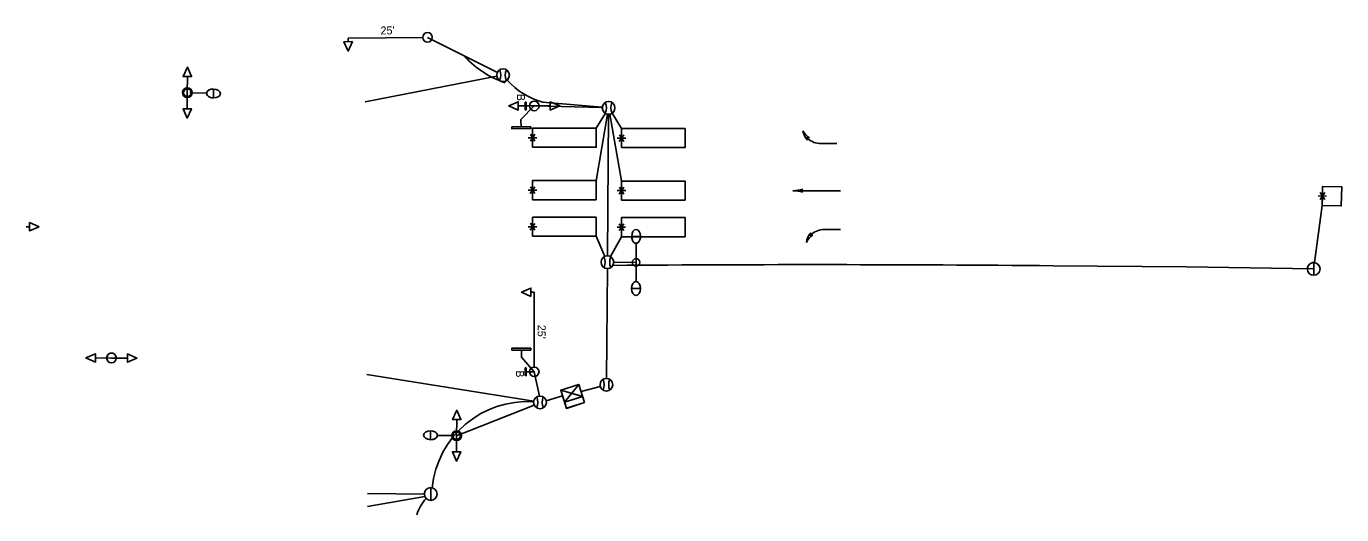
# Model space of a CAD drawing. Extents: x 596176 to 605330, y 332416 to 402398.
# Drawn here: x 602042.7 to 602456.7, y 376707.3 to 376860.8 of the extents above; entities that cross this region are included whole.
import ezdxf

# ---------------------------------------------------------------- set-up
doc = ezdxf.new("R2010")
doc.units = 0
for name, color, linetype in [('E_SIG', 7, 'Continuous'), ('P_LTG', 7, 'Continuous'), ('P_SIG', 7, 'Continuous'), ('P_SIG_Conduit', 7, 'Continuous'), ('P_SIG_IC', 7, 'Continuous'), ('P_SIG_Loops', 7, 'Continuous')]:
    doc.layers.add(name, color=color, linetype=linetype)

# ---------------------------------------------------------------- blocks, each defined once
blk = doc.blocks.new('_U234')
at = {"layer": 'E_SIG'}
for p, q in [((-0.114, 0.076), (0.114, 0.076)), ((-0.114, 0.076), (0.114, -0.076)), ((0.114, 0.076), (-0.114, -0.076))]:
    blk.add_line(p, q, dxfattribs=at)
blk.add_lwpolyline([(-0.114, 0.152), (0.114, 0.152), (0.114, -0.076), (-0.114, -0.076)], close=True, dxfattribs=at)

msp = doc.modelspace()

# ---------------------------------------------------------------- linework, layer by layer
at = {"layer": 'P_LTG'}
for p, q in [((602094.11, 376839.92), (602099.4, 376839.78)), ((602101.55, 376838.32), (602101.63, 376841.09)), ((602236.01, 376794.77), (602233.23, 376794.77)), ((602234.61, 376786.57), (602234.61, 376792.64)), ((602234.61, 376786.57), (602234.61, 376780.57)), ((602233.2, 376778.37), (602235.98, 376778.37)), ((602169.92, 376733.61), (602169.89, 376730.83)), ((602177.39, 376732.12), (602172.09, 376732.18))]:
    msp.add_line(p, q, dxfattribs=at)
for centre in [(602093.4, 376839.94), (602234.61, 376786.58), (602178.09, 376732.11)]:
    msp.add_circle(centre, 1.21, dxfattribs=at)
for centre, major_axis in [((602101.59, 376839.7), (2.18, -0.06)), ((602234.62, 376794.77), (0, 2.18)), ((602234.59, 376778.37), (0, -2.18)), ((602169.9, 376732.22), (-2.18, 0.03))]:
    msp.add_ellipse(centre, major_axis=major_axis, ratio=0.636439, start_param=1.570796, end_param=4.712389, dxfattribs=at)
for centre, major_axis in [((602101.59, 376839.7), (2.18, -0.06)), ((602234.62, 376794.77), (0, 2.18)), ((602234.59, 376778.37), (0, -2.18)), ((602169.9, 376732.22), (-2.18, 0.03))]:
    msp.add_ellipse(centre, major_axis=major_axis, ratio=0.636439, dxfattribs=at)
at = {"layer": 'P_SIG'}
for p, q in [((602143.98, 376857.04), (602167.48, 376857.33)), ((602143.98, 376857.04), (602143.99, 376856)), ((602093.37, 376845.02), (602093.35, 376839.96)), ((602093.34, 376834.9), (602093.35, 376839.96)), ((602197.5, 376835.8), (602202.56, 376835.79)), ((602198.39, 376831.49), (602202.56, 376835.79)), ((602202.56, 376835.79), (602200.06, 376835.79)), ((602207.62, 376835.77), (602202.56, 376835.79)), ((602198.39, 376831.49), (602198.42, 376829.09)), ((602289.22, 376825.73), (602288.32, 376825.91)), ((602288.57, 376824.97), (602288.32, 376825.91)), ((602297.86, 376823.97), (602292.27, 376823.97)), ((602298.93, 376809.12), (602286.36, 376809.12)), ((602043.72, 376797.81), (602042.68, 376797.81)), ((602289.64, 376795.89), (602289.4, 376794.95)), ((602290.29, 376795.13), (602289.4, 376794.95)), ((602298.93, 376796.89), (602293.34, 376796.89)), ((602447.95, 376786.54), (602447.93, 376782.54)), ((602202.56, 376777.18), (602201.52, 376777.18)), ((602202.56, 376777.18), (602202.56, 376753.68)), ((602064.42, 376756.55), (602069.48, 376756.52)), ((602198.51, 376756.73), (602198.51, 376759.13)), ((602198.51, 376756.73), (602202.57, 376752.18)), ((602074.54, 376756.51), (602069.48, 376756.52)), ((602202.56, 376752.18), (602200.06, 376752.18)), ((602217.81, 376744.42), (602210.88, 376746.39)), ((602212.1, 376742.59), (602216.59, 376748.23)), ((602217.81, 376744.42), (602212.1, 376742.59)), ((602178.16, 376737.15), (602178.14, 376732.09)), ((602178.13, 376727.04), (602178.14, 376732.09)), ((602169.99, 376715.72), (602169.97, 376711.72))]:
    msp.add_line(p, q, dxfattribs=at)
for points in [[(602145.31, 376856.02), (602144.03, 376853.04), (602142.67, 376855.98)], [(602200.06, 376836.99), (602200.06, 376834.59), (602199.74, 376834.59), (602199.74, 376836.99)], [(602195.46, 376829.18), (602201.46, 376829.26), (602201.47, 376828.66), (602195.47, 376828.58)], [(602046.68, 376797.81), (602043.72, 376796.49), (602043.72, 376799.12)], [(602201.52, 376775.86), (602198.56, 376777.18), (602201.52, 376778.5)], [(602201.47, 376759), (602195.47, 376758.99), (602195.47, 376759.6), (602201.47, 376759.6)], [(602200.06, 376753.38), (602200.06, 376750.98), (602199.74, 376750.98), (602199.74, 376753.38)], [(602218.42, 376742.52), (602212.71, 376740.68), (602210.88, 376746.39), (602216.59, 376748.23)]]:
    msp.add_lwpolyline(points, close=True, dxfattribs=at)
for points in [[(602094.68, 376845.02), (602093.37, 376847.98), (602092.05, 376845.02), (602094.68, 376845.02)], [(602093.37, 376847.98), (602094.68, 376845.02), (602092.05, 376845.02), (602093.37, 376847.98)], [(602197.5, 376837.12), (602194.54, 376835.8), (602197.5, 376834.48), (602197.5, 376837.12)], [(602194.54, 376835.8), (602197.5, 376837.12), (602197.5, 376834.48), (602194.54, 376835.8)], [(602207.62, 376834.46), (602210.58, 376835.77), (602207.62, 376837.09), (602207.62, 376834.46)], [(602210.58, 376835.77), (602207.62, 376834.46), (602207.62, 376837.09), (602210.58, 376835.77)], [(602092.02, 376834.9), (602093.34, 376831.94), (602094.66, 376834.9), (602092.02, 376834.9)], [(602093.34, 376831.94), (602092.02, 376834.9), (602094.66, 376834.9), (602093.34, 376831.94)], [(602287.16, 376809.62), (602286.36, 376809.12), (602287.16, 376808.62)], [(602447.93, 376782.54), (602447.95, 376786.54)], [(602064.42, 376757.86), (602061.46, 376756.55), (602064.42, 376755.23), (602064.42, 376757.86)], [(602061.46, 376756.55), (602064.42, 376757.86), (602064.42, 376755.23), (602061.46, 376756.55)], [(602074.54, 376755.19), (602077.5, 376756.51), (602074.54, 376757.83), (602074.54, 376755.19)], [(602077.5, 376756.51), (602074.54, 376755.19), (602074.54, 376757.83), (602077.5, 376756.51)], [(602179.47, 376737.15), (602178.16, 376740.11), (602176.84, 376737.15), (602179.47, 376737.15)], [(602178.16, 376740.11), (602179.47, 376737.15), (602176.84, 376737.15), (602178.16, 376740.11)], [(602176.81, 376727.04), (602178.13, 376724.08), (602179.45, 376727.04), (602176.81, 376727.04)], [(602178.13, 376724.08), (602176.81, 376727.04), (602179.45, 376727.04), (602178.13, 376724.08)], [(602169.97, 376711.72), (602169.99, 376715.72)]]:
    msp.add_lwpolyline(points, dxfattribs=at)
for centre, radius in [((602168.98, 376857.35), 1.5), ((602192.74, 376845.45), 2), ((602093.35, 376839.96), 1.52), ((602093.35, 376839.96), 1.52), ((602093.35, 376839.96), 1.52), ((602093.35, 376839.96), 1.52), ((602202.56, 376835.79), 1.52), ((602202.56, 376835.79), 1.52), ((602202.56, 376835.79), 1.52), ((602202.56, 376835.79), 1.52), ((602225.98, 376835.18), 2), ((602225.6, 376786.65), 2), ((602447.94, 376784.54), 2), ((602069.48, 376756.52), 1.52), ((602069.48, 376756.52), 1.52), ((602069.48, 376756.52), 1.52), ((602069.48, 376756.52), 1.52), ((602202.57, 376752.18), 1.5), ((602225.29, 376748.12), 2), ((602204.38, 376742.55), 2), ((602178.14, 376732.09), 1.52), ((602178.14, 376732.09), 1.52), ((602178.14, 376732.09), 1.52), ((602178.14, 376732.09), 1.52), ((602169.98, 376713.72), 2)]:
    msp.add_circle(centre, radius, dxfattribs=at)
for centre, radius, start, end in [((602168.98, 376857.35), 1.5, 0.7081, 180.7081), ((602168.98, 376857.35), 1.5, 180.7081, 0.7081), ((602187.67, 376845.48), 4.36, 336.6741, 22.5272), ((602197.81, 376845.49), 4.36, 157.5751, 203.4282), ((602093.35, 376839.96), 1.52, 90, 270), ((602093.35, 376839.96), 1.52, 90, 270), ((602093.35, 376839.96), 1.52, 270, 90), ((602093.35, 376839.96), 1.52, 270, 90), ((602202.56, 376835.79), 1.52, 0, 180), ((602202.56, 376835.79), 1.52, 0, 180), ((602202.56, 376835.79), 1.52, 180, 0), ((602202.56, 376835.79), 1.52, 180, 0), ((602220.91, 376835.22), 4.36, 336.6741, 22.5272), ((602231.05, 376835.23), 4.36, 157.5751, 203.4282), ((602291.79, 376830.18), 5.14, 205.2667, 239.9151), ((602293.13, 376828.97), 6.07, 189.3153, 221.1715), ((602292.67, 376829.75), 5.8, 221.4708, 266.0347), ((602283.96, 376819.61), 10.49, 270, 287.7623), ((602283.96, 376798.64), 10.49, 72.2377, 90), ((602294.21, 376791.89), 6.07, 138.8285, 170.6847), ((602292.87, 376790.68), 5.14, 120.0849, 154.7333), ((602293.74, 376791.11), 5.8, 93.9653, 138.5292), ((602220.53, 376786.69), 4.36, 336.6741, 22.5272), ((602230.67, 376786.7), 4.36, 157.5751, 203.4282), ((602447.94, 376784.54), 2, 89.7008, 180), ((602447.94, 376784.54), 2, 180, 269.7008), ((602069.48, 376756.52), 1.52, 0, 180), ((602069.48, 376756.52), 1.52, 359.9022, 179.9022), ((602069.48, 376756.52), 1.52, 179.9022, 359.9022), ((602069.48, 376756.52), 1.52, 180, 0), ((602202.57, 376752.18), 1.5, 90, 270), ((602202.57, 376752.18), 1.5, 270, 90), ((602220.22, 376748.16), 4.36, 336.6741, 22.5272), ((602230.36, 376748.17), 4.36, 157.5751, 203.4282), ((602199.31, 376742.59), 4.36, 336.6741, 22.5272), ((602209.45, 376742.6), 4.36, 157.5751, 203.4282), ((602178.14, 376732.09), 1.52, 90, 270), ((602178.14, 376732.09), 1.52, 90, 270), ((602178.14, 376732.09), 1.52, 270, 90), ((602178.14, 376732.09), 1.52, 270, 90), ((602169.98, 376713.72), 2, 89.7008, 180), ((602169.98, 376713.72), 2, 180, 269.7008)]:
    msp.add_arc(centre, radius, start, end, dxfattribs=at)
at = {"layer": 'P_SIG_Conduit'}
for points in [[(602190.95, 376846.34), (602168.98, 376857.35)], [(602149.33, 376837.1), (602190.77, 376845.09)], [(602223.98, 376835.24), (602202.56, 376835.79)], [(602205.21, 376837.01), (602223.99, 376835.36)], [(602225.97, 376833.18), (602225.61, 376788.65)], [(602234.61, 376786.57), (602227.6, 376786.63)], [(602365.89, 376785.55), (602407.85, 376785.21), (602447.94, 376784.52)], [(602225.58, 376784.65), (602225.31, 376750.12)], [(602149.85, 376751.34), (602202.41, 376742.91)], [(602204.18, 376744.54), (602202.56, 376752.18)], [(602206.3, 376743.1), (602211.46, 376744.58)], [(602217.31, 376745.99), (602223.36, 376747.59)], [(602202.55, 376741.74), (602178.12, 376732.06)]]:
    msp.add_lwpolyline(points, dxfattribs=at)
for centre, radius, start, end in [((602203.17, 376872.13), 30.65, 222.9806, 251.4252), ((602211.13, 376859.2), 22.96, 221.7805, 255.0688), ((602289.92, 368040.65), 8745.23, 89.502248, 90.410055), ((602200.4, 376712.73), 30.09, 86.205, 174.3997), ((602178.83, 376703.05), 13.86, 137.9481, 162.3423)]:
    msp.add_arc(centre, radius, start, end, dxfattribs=at)
at = {"layer": 'P_SIG_Loops'}
for p, q in [((602222.04, 376812.2), (602225.65, 376833.21)), ((602222.06, 376828.81), (602224.94, 376833.48)), ((602230.04, 376812.2), (602226.37, 376833.22)), ((602230.06, 376828.66), (602227.04, 376833.49)), ((602200.68, 376825.79), (602203.36, 376825.79)), ((602201.34, 376824.7), (602202.74, 376826.87)), ((602202.79, 376824.71), (602201.36, 376826.89)), ((602202.06, 376825.81), (602202.06, 376822.81)), ((602228.68, 376825.64), (602231.36, 376825.64)), ((602229.34, 376824.56), (602230.74, 376826.73)), ((602230.79, 376824.57), (602229.36, 376826.74)), ((602230.06, 376825.66), (602230.06, 376822.66)), ((602201.32, 376808.2), (602202.73, 376810.37)), ((602202.78, 376808.21), (602201.35, 376810.38)), ((602200.67, 376809.28), (602203.35, 376809.28)), ((602202.04, 376809.3), (602202.04, 376806.3)), ((602228.67, 376809.14), (602231.35, 376809.14)), ((602229.32, 376808.06), (602230.73, 376810.23)), ((602230.78, 376808.07), (602229.35, 376810.24)), ((602230.04, 376809.16), (602230.04, 376806.16)), ((602449.3, 376807.49), (602451.97, 376807.44)), ((602449.92, 376806.39), (602451.38, 376808.54)), ((602451.38, 376806.37), (602449.99, 376808.58)), ((602450.67, 376807.48), (602450.61, 376804.48)), ((602448.2, 376786.52), (602450.61, 376804.48)), ((602201.31, 376796.68), (602202.72, 376798.86)), ((602202.77, 376796.69), (602201.34, 376798.87)), ((602229.31, 376796.56), (602230.72, 376798.73)), ((602230.77, 376796.57), (602229.34, 376798.74)), ((602200.66, 376797.77), (602203.34, 376797.77)), ((602202.03, 376797.79), (602202.03, 376794.79)), ((602222.03, 376794.79), (602224.79, 376788.48)), ((602226.57, 376788.4), (602230.03, 376794.66)), ((602228.66, 376797.64), (602231.34, 376797.64)), ((602230.03, 376797.66), (602230.03, 376794.66)), ((602447.94, 376784.52), (602447.94, 376784.53)), ((602168.12, 376713.01), (602150.03, 376709.79)), ((602150.08, 376713.92), (602167.98, 376713.74))]:
    msp.add_line(p, q, dxfattribs=at)
for points in [[(602202.06, 376822.81), (602222.06, 376822.81), (602222.06, 376828.81), (602202.06, 376828.81)], [(602230.06, 376822.66), (602250.06, 376822.66), (602250.06, 376828.66), (602230.06, 376828.66)], [(602202.04, 376806.3), (602222.04, 376806.3), (602222.04, 376812.3), (602202.04, 376812.3)], [(602230.04, 376806.16), (602250.04, 376806.16), (602250.04, 376812.16), (602230.04, 376812.16)], [(602450.61, 376804.48), (602456.6, 376804.36), (602456.73, 376810.36), (602450.73, 376810.48)], [(602202.03, 376794.79), (602222.03, 376794.79), (602222.03, 376800.79), (602202.03, 376800.79)], [(602230.03, 376794.66), (602250.03, 376794.66), (602250.03, 376800.66), (602230.03, 376800.66)]]:
    msp.add_lwpolyline(points, close=True, dxfattribs=at)

# ---------------------------------------------------------------- block references
at = {"layer": 'P_SIG_IC', "xscale": 26.246666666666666, "yscale": 26.246666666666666, "rotation": -162.1931038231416}
msp.add_blockref('_U234', (602214.34, 376745.41), dxfattribs=at)

# ---------------------------------------------------------------- texts
at = {"layer": 'P_SIG'}
for s, rotation, p in [("25'", 0.7081, (602154.19, 376858.24)), ('B', 270, (602197.13, 376839.6)), ("25'", 270, (602203.63, 376766.95)), ('B', 270, (602196.82, 376752.64))]:
    msp.add_text(s, height=2.52, rotation=rotation, dxfattribs=at).set_placement(p)

doc.saveas('drawing.dxf')
